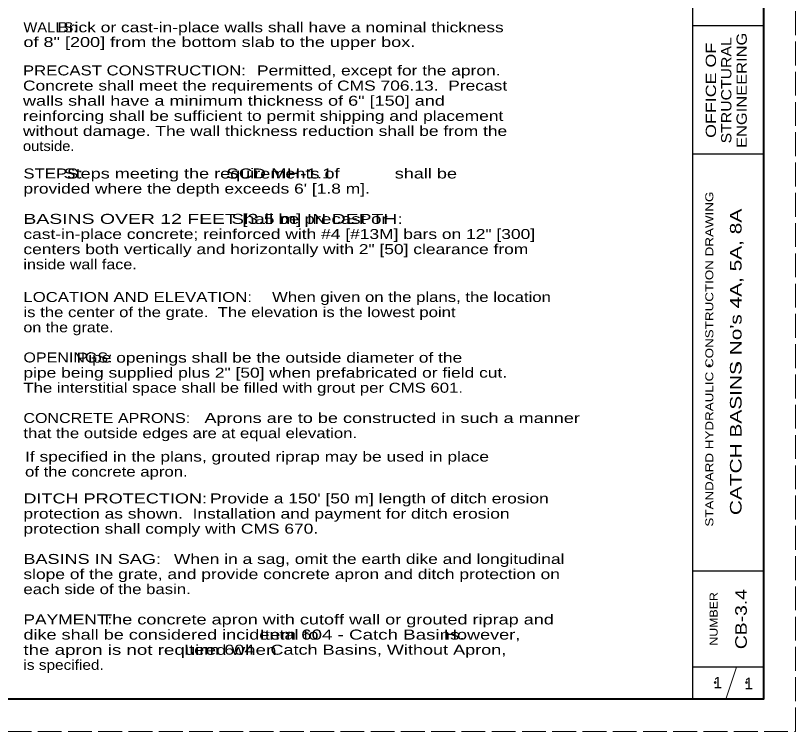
# Model space of a CAD drawing. Extents: x 1073.4 to 1107.4, y 719.4 to 741.4.
# Drawn here: x 1095.2 to 1107.36, y 719.35 to 730.51 of the extents above; entities that cross this region are included whole.
import ezdxf
from ezdxf.enums import TextEntityAlignment as Align

# ---------------------------------------------------------------- set-up
doc = ezdxf.new("R2010")
doc.units = 0
doc.header["$LTSCALE"] = 0.062
doc.header["$PDMODE"] = 32
doc.header["$PDSIZE"] = 0.031
doc.linetypes.add('LONG_DASHED', pattern=[7.5, 6, -1.5])
doc.layers.add('1', color=7, linetype='Continuous', lineweight=13)

msp = doc.modelspace()

# ---------------------------------------------------------------- linework, layer by layer
at = {"layer": '1', "lineweight": 25}
for p, q in [((1105.76142, 719.85408), (1105.76142, 740.85408)), ((1106.86142, 740.85408), (1106.86142, 719.85408)), ((1106.86142, 730.35408), (1105.76142, 730.35408)), ((1106.86142, 728.35408), (1105.76142, 728.35408)), ((1106.86142, 721.85408), (1105.76142, 721.85408)), ((1106.86142, 720.35408), (1105.76142, 720.35408))]:
    msp.add_line(p, q, dxfattribs=at)
at = {"layer": '1'}
msp.add_line((1106.27808, 719.85408), (1106.44475, 720.35408), dxfattribs=at)
at = {"layer": '1', "linetype": 'LONG_DASHED'}
msp.add_lwpolyline([(1073.36142, 719.35408), (1107.36142, 719.35408), (1107.36142, 741.35408), (1073.36142, 741.35408)], close=True, dxfattribs=at)
at = {"layer": '1', "lineweight": 25}
msp.add_lwpolyline([(1106.86142, 719.85408), (1075.36142, 719.85408), (1075.36142, 740.85408)], dxfattribs=at)
at = {"layer": '1', "lineweight": 40}
msp.add_lwpolyline([(1075.36142, 740.85408), (1106.86142, 740.85408), (1106.86142, 719.85408), (1075.36142, 719.85408)], close=True, dxfattribs=at)
msp.add_lwpolyline([(1075.36142, 740.85408), (1106.86142, 740.85408), (1106.86142, 719.85408), (1075.36142, 719.85408)], close=True, dxfattribs=at)
at = {"layer": '1'}
for p in [(1106.01883, 725.06008), (1106.45167, 725.06742), (1106.1095, 720.11783), (1106.59792, 720.11683)]:
    msp.add_point(p, dxfattribs=at)

# ---------------------------------------------------------------- texts
for s, width, p in [('WALLS:', 1.1, (1095.32158, 730.25333)), ('       Brick or cast-in-place walls shall have a nominal thickness', 1.3, (1095.32158, 730.25333)), ('of 8" [200] from the bottom slab to the upper box. ', 1.35, (1095.32158, 730.02392)), ('PRECAST CONSTRUCTION:', 1.25, (1095.31433, 729.58067)), ('Permitted, except for the apron.  ', 1.3, (1098.96417, 729.58067)), ('Concrete shall meet the requirements of CMS 706.13.  Precast', 1.3, (1095.31433, 729.34458)), ('walls shall have a minimum thickness of 6" [150] and ', 1.35, (1095.31433, 729.1085)), ('reinforcing shall be sufficient to permit shipping and placement', 1.3, (1095.31433, 728.87233)), ('without damage. The wall thickness reduction shall be from the ', 1.3, (1095.31433, 728.63683)), ('outside.', 1.1, (1095.31433, 728.40217)), ('STEPS:', 1.25, (1095.32158, 727.97433)), ('        Steps meeting the requirements of           shall be', 1.35, (1095.32158, 727.97433)), ('                                       SCD MH-1.1', 1.4, (1095.32158, 727.97433)), ("provided where the depth exceeds 6' [1.8 m].", 1.3, (1095.32158, 727.73833)), ('BASINS OVER 12 FEET [3.5 m] IN DEPTH:', 1.45, (1095.32158, 727.26633)), ('                                        Shall be precast or', 1.4, (1095.32158, 727.26633)), ('cast-in-place concrete; reinforced with #4 [#13M] bars on 12" [300]', 1.3, (1095.32158, 727.03033)), ('centers both vertically and horizontally with 2" [50] clearance from ', 1.3, (1095.32158, 726.79433)), ('inside wall face.', 1.2, (1095.32158, 726.55833)), ('LOCATION AND ELEVATION:', 1.25, (1095.32158, 726.0485)), ('When given on the plans, the location', 1.25, (1099.19925, 726.0485)), ('is the center of the grate.  The elevation is the lowest point', 1.25, (1095.32158, 725.8125)), ('on the grate.', 1.2, (1095.32158, 725.5765)), ('OPENINGS:', 1.2, (1095.32158, 725.10583)), ('           Pipe openings shall be the outside diameter of the', 1.3, (1095.32158, 725.10317)), ('pipe being supplied plus 2" [50] when prefabricated or field cut. ', 1.3, (1095.32158, 724.8685)), ('The interstitial space shall be filled with grout per CMS 601.', 1.25, (1095.32158, 724.63383)), ('CONCRETE APRONS:', 1.2, (1095.32158, 724.16183)), ('Aprons are to be constructed in such a manner', 1.35, (1098.14508, 724.16183)), ('that the outside edges are at equal elevation.', 1.25, (1095.32158, 723.92583)), ('If specified in the plans, grouted riprap may be used in place ', 1.3, (1095.34675, 723.56075)), ('of the concrete apron.', 1.25, (1095.34675, 723.32608)), ('DITCH PROTECTION: ', 1.35, (1095.32158, 722.90833)), ("Provide a 150' [50 m] length of ditch erosion", 1.3, (1098.23158, 722.90833)), ('protection as shown.  Installation and payment for ditch erosion', 1.3, (1095.32158, 722.671)), ('protection shall comply with CMS 670.', 1.3, (1095.32158, 722.43633)), ('BASINS IN SAG:', 1.35, (1095.32158, 721.96433)), ('When in a sag, omit the earth dike and longitudinal', 1.3, (1097.6695, 721.96433)), ('slope of the grate, and provide concrete apron and ditch protection on', 1.3, (1095.32158, 721.72833)), ('each side of the basin.', 1.25, (1095.32158, 721.49433)), ('PAYMENT: ', 1.3, (1095.32158, 721.02167)), ('    The concrete apron with cutoff wall or grouted riprap and', 1.35, (1096.22117, 721.02167)), ('dike shall be considered incidental to                         However, ', 1.35, (1095.32158, 720.78567)), ('                      Item 604 - Catch Basins.', 1.4, (1097.21925, 720.78558)), ('                         Item 604 - Catch Basins, Without Apron,', 1.35, (1095.87208, 720.54967)), ('the apron is not required when                                     ', 1.4, (1095.32158, 720.54767)), ('is specified.', 1.15, (1095.32158, 720.31367))]:
    msp.add_text(s, height=0.156, dxfattribs=dict(at, width=width)).set_placement(p)
for s, height, width, p in [('ENGINEERING', 0.16, 1.2, (1106.60317, 729.34862)), ('OFFICE OF', 0.16, 1.3, (1106.12317, 729.34854)), ('STRUCTURAL', 0.16, 1.15, (1106.36317, 729.34854)), ('STANDARD HYDRAULIC CONSTRUCTION DRAWING', 0.125, 1.25, (1106.08133, 725.15812)), ("CATCH BASINS No's 4A, 5A, 8A", 0.18, 1.35, (1106.52108, 725.11421)), ('NUMBER', 0.125, 1.15, (1106.14842, 721.10817)), ('CB-3.4', 0.18, 1.25, (1106.60325, 721.10442))]:
    msp.add_text(s, height=height, rotation=90, dxfattribs=dict(at, width=width)).set_placement(p, align=Align.CENTER)
for p in [(1106.14927, 720.02417), (1106.6321, 720.01158)]:
    msp.add_text('1', height=0.18, dxfattribs=at).set_placement(p, align=Align.CENTER)

doc.saveas('drawing.dxf')
